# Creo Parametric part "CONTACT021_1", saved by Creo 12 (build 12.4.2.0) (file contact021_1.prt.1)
Units: Custom; MM, KILOGRAM, SECS

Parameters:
  PTC_WM_ITERATION = "0"
  PTC_WM_VERSION = "-.0"
  PTC_WM_LIFECYCLE_STATE = "In Work"
  PTC_WM_LIFECYCLE = "MO_CADDocument"
  PTC_WM_CREATED_BY = "Maximilian Roepper (Z0017RMS: MO)"
  PTC_WM_CREATED_ON = "18-Sep-26 11:36:42 AM"
  PTC_WM_MODIFIED_BY = "Maximilian Roepper (Z0017RMS: MO)"
  PTC_WM_MODIFIED_ON = "18-Sep-26 11:36:46 AM"
  PDMLINKNUMBER = "PDM000071454847"
  PTC_WM_NAME = "contact021_1.prt"
  PTC_WM_NUMBER = "PDM000071454847"

Other parameters: WEIGHT, WEIGHT_FACTOR, WEIGHT_ADD, _MASS_TEMP, _DIFF_TEMP, MC_ERRORS, SUPPLIER

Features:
  1. coordinate system
  2. datum plane "PRT_YZ"
  3. datum plane "PRT_XY"
  4. datum plane "PRT_XZ"
  5. coordinate system
  6. datum axis
  7. datum axis
  8. datum axis
  9. coordinate system
  10. imported feature

Other named items: PRT, SIEMENS_MO, DRW_VIEW_ORG, PRT_X, PRT_Y, PRT_Z, CS0, ROUGH_GROB

Layers: 00_STD_CSYS-KSYS, 01_STD_PLANES-EBENEN, 02_STD_AXES-ACHSEN, 03_STD_CSYS-KSYS, 24_IMPORT_FEAT-IMPORT_KE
